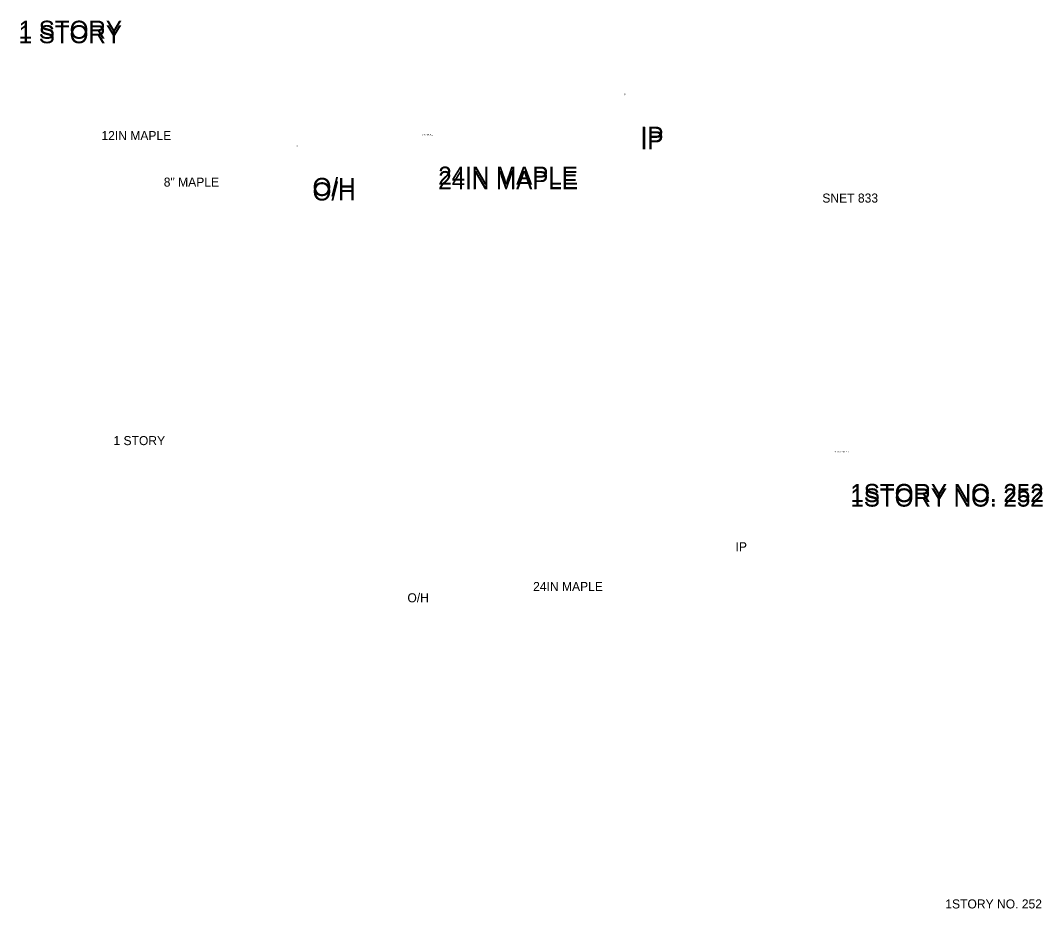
# Model space of a CAD drawing. Extents: x 5447 to 709667, y 4528 to 375472.
# Drawn here: x 708865.6 to 709046.7, y 373667.7 to 373825.1 of the extents above; entities that cross this region are included whole.
import ezdxf

# ---------------------------------------------------------------- set-up
doc = ezdxf.new("R2010")
doc.units = 0
doc.layers.add('SV_SURVEY_NOTES', color=7, linetype='Continuous')

msp = doc.modelspace()

# ---------------------------------------------------------------- texts
at = {"layer": 'SV_SURVEY_NOTES'}
for s, height, p in [('1 STORY', 3.2, (708865.31, 373821.86)), ('1 STORY', 3.2, (708865.31, 373821.86)), ('1 STORY', 3.2, (708865.31, 373821.86)), ('1 STORY', 3.2, (708865.31, 373821.86)), ('1 STORY', 3.2, (708865.31, 373821.86)), ('1 STORY', 3.2, (708865.32, 373821.86)), ('1 STORY', 3.2, (708865.32, 373821.86)), ('1 STORY', 3.2, (708865.32, 373821.86)), ('1 STORY', 3.2, (708865.31, 373821.06)), ('1 STORY', 3.2, (708865.31, 373821.06)), ('1 STORY', 3.2, (708865.32, 373821.06)), ('IP', 0.25, (708972.53, 373811.85)), ('12IN MAPLE', 1.6, (708879.98, 373803.9)), ('24IN MAPLE', 0.25, (708936.72, 373804.75)), ('IP', 3.2, (708975.48, 373803.08)), ('IP', 3.2, (708975.48, 373803.08)), ('IP', 3.2, (708975.48, 373803.08)), ('IP', 3.2, (708975.48, 373802.28)), ('IP', 3.2, (708975.5, 373803.05)), ('IP', 3.2, (708975.5, 373803.05)), ('IP', 3.2, (708975.5, 373803.05)), ('IP', 3.2, (708975.5, 373803.05)), ('IP', 3.2, (708975.5, 373803.05)), ('IP', 3.2, (708975.5, 373802.25)), ('IP', 3.2, (708975.5, 373802.25)), ('O/H', 0.25, (708914.46, 373802.74)), ('24IN MAPLE', 3.2, (708939.64, 373796)), ('24IN MAPLE', 3.2, (708939.64, 373796)), ('24IN MAPLE', 3.2, (708939.64, 373796)), ('24IN MAPLE', 3.2, (708939.64, 373796)), ('24IN MAPLE', 3.2, (708939.64, 373796)), ('24IN MAPLE', 3.2, (708939.65, 373796.01)), ('24IN MAPLE', 3.2, (708939.65, 373796.01)), ('24IN MAPLE', 3.2, (708939.65, 373796.01)), ('24IN MAPLE', 3.2, (708939.64, 373795.2)), ('24IN MAPLE', 3.2, (708939.64, 373795.2)), ('24IN MAPLE', 3.2, (708939.65, 373795.21)), ('8" MAPLE', 1.6, (708891.02, 373795.66)), ('O/H', 3.2, (708917.38, 373794)), ('O/H', 3.2, (708917.38, 373794)), ('O/H', 3.2, (708917.38, 373794)), ('O/H', 3.2, (708917.38, 373794)), ('O/H', 3.2, (708917.38, 373794)), ('O/H', 3.2, (708917.38, 373793.2)), ('O/H', 3.2, (708917.38, 373793.2)), ('O/H', 3.2, (708917.39, 373794.01)), ('O/H', 3.2, (708917.39, 373794.01)), ('O/H', 3.2, (708917.39, 373794.01)), ('O/H', 3.2, (708917.39, 373793.21)), ('SNET 833', 1.6, (709007.67, 373792.83)), ('1 STORY', 1.6, (708882.11, 373749.85)), ('1STORY NO. 252', 0.25, (709009.68, 373748.56)), ('1STORY NO. 252', 3.2, (709012.63, 373739.78)), ('1STORY NO. 252', 3.2, (709012.63, 373739.78)), ('1STORY NO. 252', 3.2, (709012.63, 373739.78)), ('1STORY NO. 252', 3.2, (709012.63, 373738.98)), ('1STORY NO. 252', 3.2, (709012.64, 373739.75)), ('1STORY NO. 252', 3.2, (709012.64, 373739.75)), ('1STORY NO. 252', 3.2, (709012.64, 373739.75)), ('1STORY NO. 252', 3.2, (709012.64, 373739.75)), ('1STORY NO. 252', 3.2, (709012.64, 373739.75)), ('1STORY NO. 252', 3.2, (709012.64, 373738.95)), ('1STORY NO. 252', 3.2, (709012.64, 373738.95)), ('IP', 1.6, (708992.3, 373731.05)), ('24IN MAPLE', 1.6, (708956.44, 373724)), ('O/H', 1.6, (708934.18, 373722)), ('1STORY NO. 252', 1.6, (709029.45, 373667.75))]:
    msp.add_text(s, height=height, dxfattribs=at).set_placement(p)

doc.saveas('drawing.dxf')
